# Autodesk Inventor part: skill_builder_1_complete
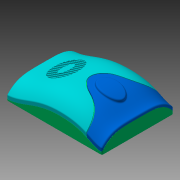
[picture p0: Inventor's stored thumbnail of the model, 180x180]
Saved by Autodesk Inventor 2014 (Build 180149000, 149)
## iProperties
Created: 2009-03
Part Number: skill_builder_1_complete
Document SubType Name: Modeling
Designer: PN
Density: 1 g/cm^3
Material: Generic
Appearance: 0,255,128
Author: PN
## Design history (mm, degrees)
sketch "Sketch1"
  geometry: L1 (-70, -12)-(50, -12); L2 (50, -12)-(50, 3); L3 (50, 3)-(-70, 0); L4 (-70, 0)-(-70, -12); 1 further point
  constraints: 8 end point, 1 horizontal, 1 horizontal alignment, 1 parallel, 1 perpendicular
  dimensions: "d0" = 12 distance of L3.end L1.start; "d1" = 15 distance of L1.end L2.end; "d2" = 70 horizontal distance of L1.start point (0, 0); "d3" = 120 distance between parallel lines of L2 L4
extrude "Extrusion1" new body sketch "Sketch1" stored distance "d4" = 90; taper "d5" = 0 deg
sketch "Sketch2"
  geometry: L1 (-70, -12)-(-70, 0) reference; L2 (50, 3)-(50, -12) reference; L3 (-12.387, 9.326)-(12.387, 8.674); L4 (-82.391, -6)-(-57.609, -6); L5 (37.609, -4.5)-(62.391, -4.5); A1 r 110 centre (-2.894, -100.962) between (9.858, 8.296) and (-9.881, 8.816); A2 r 29.927 centre (-70, 23.927) between (-79.41, -4.482) and (-60.59, -4.482); A3 r 19.691 centre (50, 15.191) between (41.146, -2.397) and (58.854, -2.397); 4 further points
  constraints: 8 midpoint, 6 end point, 5 point on circle, 4 horizontal, 3 centre point, 1 tangent, 1 vertical alignment, 7 other
  dimensions: "d6" = 9 distance of point (0, 9) point (0, 0); "d7" = 110 radius of A1; "d8" = 10 dimension on L4.start L4.end; "d9" = 10 dimension on L5.start L5.end; "d10" = 10 dimension on L3.start L3.end
sketch "Sketch3"
  geometry: 3 further points
sketch "Sketch4"
  geometry: L1 (0, 0)-(0, 12) reference; L2 (-90, 12)-(0, 12) reference; L3 (-90, 12)-(-90, 0) reference; L4 (-53.739, 19)-(-36.261, 19); A1 r 10000 centre (-45, -9981) between (-38.009, 18.998) and (-51.991, 18.998); 5 further points
  constraints: 5 midpoint, 2 end point, 1 centre point, 1 horizontal, 1 point on circle, 1 vertical alignment, 4 other
  dimensions: "d11" = 7 distance of point (-45, 12) point (-45, 19)
feature "LoftSrf1" sketch "Sketch2", "Sketch3", "Sketch4" dims "d12" = 0, "d13" = 90 deg, "d14" = 0, "d15" = 90 deg, "d16" = 0, "d17" = 90 deg
feature "Replace Face1"
shell "Shell1" dims "d48" = 2
feature "OffsetSrf1" dims "d18" = 3, "d19" = 5
feature "Extend1" dims "d20" = 7.5
split "Split1"
  body "Solid1"
sketch "Sketch5"
  geometry: L1 (120, 0)-(0, 0) reference; L2 (0, -90)-(120, -90) reference; L3 (100, -97.611)-(100, -82.389); L4 (100, -10.013)-(100, 10.013); L5 (59.587, -55.411)-(60.413, -34.589); L6 (95.638, -75.394)-(78.362, -63.741); L7 (78.362, -27.394)-(95.638, -15.741); A1 r 12.849 centre (87.151, -90) between (98.762, -95.502) and (98.762, -84.498); A2 r 28.064 centre (71.936, 0) between (98.922, -7.703) and (98.922, 7.703); A3 r 12 centre (71.991, -45.475) between (62.425, -38.23) and (61.881, -51.94); A4 r 39.244 centre (65.055, -102.103) between (93.281, -74.837) and (79.761, -65.718); A5 r 44.643 centre (62.036, 15.443) between (79.783, -25.521) and (93.369, -16.357); 6 further points
  constraints: 10 end point, 10 midpoint, 7 point on circle, 5 centre point, 4 vertical, 2 point on line, 2 vertical alignment, 1 tangent, 13 other
  dimensions: "d21" = 33 horizontal distance of point (87, -69.568) L2.end; "d22" = 20 distance of point (100, 0) L1.start; "d23" = 10 distance of point (70, -45) point (60, -45); "d24" = 10 dimension on L6.start L6.end; "d25" = 10 dimension on L7.start L7.end; "d26" = 10 dimension on L5.start L5.end; "d27" = 34 deg angle of L2 L6; "d28" = 34 deg angle of L1 L7 (= d27); "d29" = 48 distance of point (87, -21.568) point (87, -69.568); "d30" = 12 radius of A3
extrude_surface "ExtrusionSrf1" sketch "Sketch5" dims "d31" = 40, "d32" = 0
split "Split2"
  body "Solid3"
feature "OffsetSrf2" dims "d33" = 1, "d34" = 1
split "Split3"
workplane "Work Plane1"
sketch "Sketch6" dims "d36" = 10, "d37" = 5, "d38" = 10, "d77" = 10
  geometry: L1 (14.407, -27)-(46.479, -27); L2 (70, -108.457)-(70, 18.457) reference; L3 (-24.333, -45)-(144.31, -45) reference; L4 (14.407, -30.273)-(46.479, -30.273); L5 (14.407, -33.545)-(46.479, -33.545); L6 (14.407, -36.818)-(46.479, -36.818); L7 (14.407, -40.091)-(46.479, -40.091); L8 (14.407, -43.364)-(46.479, -43.364); L9 (14.407, -46.636)-(46.479, -46.636); L10 (14.407, -49.909)-(46.479, -49.909); L11 (14.407, -53.182)-(46.479, -53.182); L12 (14.407, -56.455)-(46.479, -56.455); L13 (14.407, -59.727)-(46.479, -59.727); L14 (14.407, -63)-(46.479, -63); 2 further points; 1 other entity
  constraints: 24 end point, 1 horizontal, 1 horizontal alignment, 1 vertical, 35 other
  dimensions: "d39" = 18 distance from line of L1 point (30, -45); "d71" = 40 distance of point (30, -45) point (70, -45); "d74" = 3.27273 distance of L1.start L4.start
feature "Grill2" sketch "Sketch6" dims "d80" = 2, "d81" = 0, "d82" = 1, "d83" = 2, "d84" = 0, "d85" = 1, "d86" = 0, "d87" = 0, "d88" = 1, "d89" = 0, "d90" = 0, "d91" = 0, "d92" = 58.46723
fillet "Fillet1" dims "d93" = 2
sketch "Sketch7"
  geometry: 2 further points; 1 other entity
  constraints: 1 horizontal alignment, 2 other
emboss "Emboss1" sketch "Sketch7" dims "d0" = 12, "d1" = 15, "d2" = 70, "d3" = 120, "d6" = 9, "d7" = 110, "d8" = 10, "d9" = 10, "d10" = 10, "d94" = 3, "d95" = 0
fillet "Fillet2" dims "d96" = 2
body "Srf1"
body "Srf2"
body "Srf3"
body "Srf4"
body "Solid2"
body "Solid4"
body "Solid5"
other parameters: "d79" = 1
